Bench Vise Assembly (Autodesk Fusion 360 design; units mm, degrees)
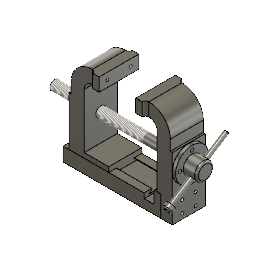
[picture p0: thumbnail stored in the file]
sketch "Sketch1" plane through (0, 0, 0) normal (0, 0, 1) x axis (1, 0, 0)
  line L1 (295, 0) -> (0, 0)
  line L2 (295, 64) -> (295, 0)
  line L3 (275, 64) -> (295, 64)
  line L4 (275, 27) -> (275, 64)
  line L5 (245, 27) -> (275, 27)
  line L6 (245, 42) -> (245, 27)
  line L7 (0, 42) -> (245, 42)
  line L8 (0, 0) -> (0, 42)
  point P1 (0, 0)
  point P2 (0, 0)
  point P3 (295, 0)
  point P4 (295, 64)
  point P5 (275, 64)
  point P9 (0, 42)
  point P6 (275, 27)
  point P7 (245, 27)
  coincident P1 P2
  horizontal L1
  perpendicular L1 L2
  perpendicular L2 L3
  perpendicular L3 L4
  perpendicular L4 L5
  perpendicular L5 L6
  perpendicular L6 L7
  perpendicular L1 L8
  dimension "d1" distance P2 P3 = 295
  dimension "d2" distance P3 P4 = 64
  dimension "d3" distance P4 P5 = 20
  dimension "d4" distance L1 L5 = 27
  dimension "d5" distance P2 P9 = 42
  dimension "d6" distance P6 P7 = 30
extrude "Extrude1" new body sketch "Sketch1" distance 100
sketch "Sketch2" plane through (0, 0, 0) normal (-1, 0, 0) x axis (0, 0, 1)
  line L1 (50, 0) -> (-50, 0)
  line L2 (50, 42) -> (50, 0)
  line L3 (-50, 42) -> (50, 42)
  line L4 (-50, 0) -> (-50, 42)
  line L5 (0, 68.3047) -> (0, 0)
  line L6 (-27, 40) -> (-27, 42)
  line L7 (-35, 32) -> (-27, 40)
  line L8 (35, 32) -> (-35, 32)
  line L9 (27, 40) -> (35, 32)
  line L10 (27, 42) -> (27, 40)
  line L11 (27, 42) -> (-27, 42)
  point P1 (0, 0)
  point P6 (0, 0)
  point P8 (-27, 42)
  point P13 (27, 42)
  point P10 (-35, 32)
  point P11 (35, 32)
  point P9 (-27, 40)
  coincident P1 P6
  perpendicular L1 L5
  coincident L3 P8
  perpendicular L3 L6
  perpendicular L6 L8
  perpendicular L7 L9
  coincident L3 P13
  vertical L10
  symmetric L5 L6 L10
  equal L6 L10
  symmetric L5 P10 P11
  dimension "d9" distance P8 P13 = 54
  dimension "d10" distance P10 P11 = 70
  dimension "d11" distance P8 P9 = 2
extrude "Extrude2" cut sketch "Sketch2" profile of L3 L6 L7 L8 L9 L10 L11 to an object
sketch "Sketch3" plane through (295, 0, 0) normal (1, 0, 0) x axis (0, 0, -1)
  line L1 (-50, 64) -> (50, 64)
  line L2 (-50, 0) -> (-50, 64)
  line L3 (50, 0) -> (-50, 0)
  line L4 (50, 64) -> (50, 0)
  line L5 (0, 88.8318) -> (0, 0)
  point P1 (0, 0)
  point P6 (0, 0)
  point P8 (-20, 52)
  point P9 (20, 52)
  point P10 (20, 16)
  point P11 (-20, 16)
  coincident P1 P6
  perpendicular L3 L5
  symmetric L5 P8 P9
  symmetric L5 P10 P11
  vertical P8 P11
  dimension "d14" distance P8 P9 = 40
  dimension "d15" distance P8 P11 = 36
  dimension "d16" distance L3 P11 = 16
hole "Hole1" HoleDepth 20 HoleDiameter 9 TipAngle 118
sketch "Sketch1" plane through (0, 0, 0) normal (-1, 0, 0) x axis (0, 0, 1)
  line L1 (-27, 42) -> (-27, 40)
  line L2 (-50, 42) -> (-27, 42)
  line L3 (-50, 0) -> (-50, 42)
  line L4 (50, 0) -> (-50, 0)
  line L5 (50, 42) -> (50, 0)
  line L6 (27, 42) -> (50, 42)
  line L7 (27, 40) -> (27, 42)
  line L8 (35, 32) -> (27, 40)
  line L9 (-35, 32) -> (35, 32)
  line L10 (-27, 40) -> (-35, 32)
  line L11 (-27, 42) -> (-27, 40)
  line L12 (-27, 40) -> (-35, 32)
  line L13 (-35, 32) -> (35, 32)
  line L14 (35, 32) -> (27, 40)
  line L15 (27, 40) -> (27, 42)
  line L16 (-50, 42) -> (-27, 42)
  line L17 (27, 42) -> (50, 42)
  line L18 (-50, 57) -> (-50, 42)
  line L19 (50, 57) -> (-50, 57)
  line L20 (50, 42) -> (50, 57)
  point P18 (-50, 42)
  point P20 (-50, 42)
  point P19 (50, 42)
  point P23 (50, 42)
  coincident P18 P20
  perpendicular L16 L18
  perpendicular L5 L19
  coincident P19 P23
  perpendicular L17 L20
  dimension "d20" distance L13 L19 = 25
extrude "Extrude1" new body sketch "Sketch1" profile of L1 L2 L6 L7 L8 L9 L10 L11 L12 L13 L14 L15 L16 L17 L18 L19 L20 against normal blind 120
sketch "Sketch2" plane through (0, 0, 50) normal (0, 0, 1) x axis (1, 0, 0)
  line L1 (0, 42) -> (0, 57)
  line L2 (120, 42) -> (0, 42)
  line L3 (120, 57) -> (120, 42)
  line L4 (0, 57) -> (120, 57)
  line L5 (0, 190) -> (0, 57)
  line L6 (6, 190) -> (0, 190)
  line L7 (6, 222) -> (6, 190)
  line L8 (101, 287) -> (71, 287)
  line L9 (101, 247) -> (101, 287)
  line L10 (71, 247) -> (101, 247)
  line L11 (46, 57) -> (46, 222)
  line L12 (0, 57) -> (46, 57)
  arc A1 centre (71, 222) radius 65 clockwise from (6, 222) to (71, 287)
  arc A2 centre (71, 222) radius 25 clockwise from (46, 222) to (71, 247)
  point P2 (0, 57)
  point P6 (0, 57)
  point P17 (46, 57)
  point P7 (0, 190)
  point P8 (6, 190)
  point P9 (6, 222)
  point P10 (71, 287)
  point P12 (101, 287)
  coincident P2 P6
  perpendicular L4 L5
  perpendicular L5 L6
  perpendicular L6 L7
  tangent L7 A1
  horizontal L8
  tangent A1 L8
  perpendicular L8 L9
  perpendicular L9 L10
  tangent L10 A2
  coincident L4 P17
  perpendicular L5 L12
  vertical L11
  concentric A1 A2
  tangent A2 L11
  dimension "d24" distance P7 P8 = 6
  dimension "d25" distance P8 P9 = 32
  dimension "d26" radius A1 = 65
  dimension "d27" distance P10 P12 = 30
  dimension "d28" radius A2 = 25
  dimension "d65" distance L8 L12 = 230
extrude "Extrude2" add sketch "Sketch2" profile of L4 L5 L6 L7 A1 L8 L9 L10 A2 L11 L12 to an object
sketch "Sketch3" plane through (0, 0, 50) normal (0, 0, 1) x axis (1, 0, 0)
  line L1 (0, 42) -> (0, 190)
  line L2 (120, 42) -> (0, 42)
  line L3 (120, 57) -> (120, 42)
  line L4 (46, 57) -> (120, 57)
  line L5 (46, 222) -> (46, 57)
  line L6 (101, 247) -> (71, 247)
  line L7 (101, 287) -> (101, 247)
  line L8 (71, 287) -> (101, 287)
  line L9 (6, 190) -> (6, 222)
  line L10 (0, 190) -> (6, 190)
  line L11 (81, 287) -> (101, 287)
  line L12 (81, 247) -> (81, 287)
  line L13 (101, 247) -> (81, 247)
  line L14 (101, 287) -> (101, 247)
  arc A1 centre (71, 222) radius 25 clockwise from (46, 222) to (71, 247)
  arc A2 centre (71, 222) radius 65 clockwise from (6, 222) to (71, 287)
  point P17 (81, 247)
  point P11 (101, 287)
  point P15 (101, 287)
  point P16 (81, 287)
  horizontal L11
  vertical L12
  horizontal L13
  vertical L14
  coincident L6 P17
  coincident P11 P15
  dimension "d31" distance P15 P16 = 20
extrude "Extrude3" add sketch "Sketch3" profile of L6 L7 L8 L11 L12 L13 L14 along normal blind 10
mirror "Mirror1"
fillet "Fillet1" radius 10
sketch "Sketch4" plane through (46, 0, 0) normal (1, 0, 0) x axis (0, 0, -1)
  line L1 (50, 222) -> (50, 57)
  line L2 (-50, 222) -> (50, 222)
  line L3 (-50, 57) -> (-50, 222)
  line L4 (50, 57) -> (-50, 57)
  line L5 (-50, 57) -> (50, 57)
  circle C1 centre (0, 139) radius 15
  point P1 (0, 0)
  point P6 (0, 139)
  vertical P1 P6
  dimension "d36" diameter C1 = 30
  dimension "d37" distance P6 L5 = 82
extrude "Extrude4" cut sketch "Sketch4" profile of C1 no distance stored
sketch "Sketch5" plane through (101, 0, 0) normal (1, 0, 0) x axis (0, 0, -1)
  line L1 (-60, 287) -> (60, 287)
  line L2 (-60, 247) -> (-60, 287)
  line L3 (60, 247) -> (-60, 247)
  line L4 (60, 287) -> (60, 247)
  line L5 (0, 297.2184) -> (0, 0)
  point P1 (0, 0)
  point P6 (0, 0)
  point P8 (-35, 267)
  point P9 (35, 267)
  coincident P1 P6
  perpendicular L1 L5
  symmetric L5 P8 P9
  dimension "d39" distance P8 P9 = 70
  dimension "d40" distance L3 P8 = 20
hole "Hole1" HoleDepth 12 HoleDiameter 9 TipAngle 118
sketch "Sketch1" plane through (0, 0, 50) normal (0, 0, 1) x axis (1, 0, 0)
  line L1 (0, 0) -> (0, 42)
  line L2 (295, 0) -> (0, 0)
  line L3 (295, 64) -> (295, 0)
  line L4 (275, 64) -> (295, 64)
  line L5 (275, 27) -> (275, 64)
  line L6 (245, 27) -> (275, 27)
  line L7 (245, 42) -> (245, 27)
  line L8 (0, 42) -> (245, 42)
  line L9 (275, 64) -> (295, 64)
  line L10 (295, 64) -> (295, 0)
  line L11 (330, 0) -> (295, 0)
  line L12 (330, 190) -> (330, 0)
  line L13 (324, 190) -> (330, 190)
  line L14 (324, 222) -> (324, 190)
  line L15 (229, 287) -> (259, 287)
  line L16 (229, 247) -> (229, 287)
  line L17 (259, 247) -> (229, 247)
  line L18 (284, 64) -> (284, 222)
  arc A1 centre (259, 222) radius 65 clockwise from (259, 287) to (324, 222)
  arc A2 centre (259, 222) radius 25 clockwise from (259, 247) to (284, 222)
  point P4 (295, 0)
  point P13 (295, 0)
  point P25 (284, 64)
  point P14 (330, 0)
  point P15 (330, 190)
  point P16 (324, 190)
  point P17 (324, 222)
  point P18 (259, 287)
  point P20 (229, 287)
  coincident P4 P13
  perpendicular L10 L11
  perpendicular L11 L12
  perpendicular L12 L13
  perpendicular L13 L14
  tangent L14 A1
  perpendicular L10 L15
  perpendicular L15 L16
  perpendicular L16 L17
  tangent L17 A2
  tangent A1 L15
  concentric A1 A2
  vertical L18
  tangent A2 L18
  coincident L4 P25
  dimension "d44" distance P14 P15 = 190
  dimension "d45" distance P13 P14 = 35
  dimension "d46" distance P16 P17 = 32
  dimension "d47" radius A1 = 65
  dimension "d48" distance P18 P20 = 30
  dimension "d49" radius A2 = 25
  dimension "d51" distance L12 L18 = 46
extrude "Extrude1" new body sketch "Sketch1" profile of L3 L4 L9 L10 L11 L12 L13 L14 A1 L15 L16 L17 A2 L18 to an object
sketch "Sketch2" plane through (0, 0, 50) normal (0, 0, 1) x axis (1, 0, 0)
  line L1 (330, 0) -> (295, 0)
  line L2 (330, 190) -> (330, 0)
  line L3 (324, 190) -> (330, 190)
  line L4 (324, 222) -> (324, 190)
  line L5 (229, 287) -> (259, 287)
  line L6 (229, 247) -> (229, 287)
  line L7 (259, 247) -> (229, 247)
  line L8 (284, 64) -> (284, 222)
  line L9 (295, 64) -> (284, 64)
  line L10 (295, 0) -> (295, 64)
  line L11 (249, 287) -> (229, 287)
  line L12 (249, 247) -> (249, 287)
  line L13 (229, 247) -> (249, 247)
  line L14 (229, 287) -> (229, 247)
  arc A1 centre (259, 222) radius 65 clockwise from (259, 287) to (324, 222)
  arc A2 centre (259, 222) radius 25 clockwise from (259, 247) to (284, 222)
  point P17 (249, 247)
  point P9 (229, 287)
  point P15 (229, 287)
  point P16 (249, 287)
  horizontal L11
  vertical L12
  horizontal L13
  vertical L14
  coincident L7 P17
  coincident P9 P15
  dimension "d54" distance P15 P16 = 20
extrude "Extrude2" add sketch "Sketch2" profile of L5 L6 L7 L11 L12 L13 L14 along normal blind 10
mirror "Mirror1"
fillet "Fillet1" radius 10
sketch "Sketch3" plane through (229, 0, 0) normal (-1, 0, 0) x axis (0, 0, 1)
  line L1 (60, 247) -> (-60, 247)
  line L2 (60, 287) -> (60, 247)
  line L3 (-60, 287) -> (60, 287)
  line L4 (-60, 247) -> (-60, 287)
  line L5 (0, 317.3095) -> (0, 0)
  point P1 (0, 0)
  point P6 (0, 0)
  point P8 (-35, 267)
  point P9 (35, 267)
  coincident P1 P6
  perpendicular L3 L5
  symmetric L5 P8 P9
  dimension "d59" distance P8 P9 = 70
  dimension "d61" distance L1 P8 = 20
hole "Hole1" HoleDepth 12 HoleDiameter 9 TipAngle 118
sketch "Sketch5" plane through (330, 0, 0) normal (1, 0, 0) x axis (0, 0, -1)
  line L1 (50, 190) -> (50, 0)
  line L2 (-50, 190) -> (50, 190)
  line L3 (-50, 0) -> (-50, 190)
  line L4 (50, 0) -> (-50, 0)
  circle C1 centre (0, 139) radius 15
extrude "Extrude3" cut sketch "Sketch5" profile of C1 to an object
sketch "Sketch6" plane through (330, 0, 0) normal (1, 0, 0) x axis (0, 0, -1)
  line L1 (50, 190) -> (50, 0)
  line L2 (-50, 190) -> (50, 190)
  line L3 (-50, 0) -> (-50, 190)
  line L4 (50, 0) -> (-50, 0)
  circle C1 centre (0, 139) radius 15
  circle C2 centre (0, 176) radius 5
  circle C3 centre (0, 139) radius 37
  point P7 (0, 176)
  point P8 (0, 139)
  concentric C1 C3
  coincident P7 C3
  vertical P7 P8
  dimension "d70" diameter C3 = 74
  dimension "d71" diameter C2 = 10
extrude "Extrude4" cut sketch "Sketch6" profile of C2 to an object
circular_pattern "C-Pattern1" TotalAngle 360
sketch "Sketch1" plane through (330, 0, 0) normal (1, 0, 0) x axis (0, 0, -1)
  line L1 (50, 190) -> (50, 0)
  line L2 (-50, 190) -> (50, 190)
  line L3 (-50, 0) -> (-50, 190)
  line L4 (50, 0) -> (-50, 0)
  circle C1 centre (-37, 139) radius 5
  circle C2 centre (0, 102) radius 5
  circle C3 centre (37, 139) radius 5
  circle C4 centre (0, 176) radius 5
  circle C5 centre (0, 139) radius 15
  circle C6 centre (0, 139) radius 50
  circle C7 centre (-37, 139) radius 5
  circle C8 centre (0, 176) radius 5
  circle C9 centre (37, 139) radius 5
  circle C10 centre (0, 102) radius 5
  circle C11 centre (0, 139) radius 15
  concentric C5 C6
  dimension "d76" diameter C6 = 100
extrude "Extrude1" new body sketch "Sketch1" profile of C1 C2 C3 C4 C5 C6 C7 C8 C9 C10 C11 along normal blind 10
sketch "Sketch1" plane through (340, 0, 0) normal (1, 0, 0) x axis (0, 0, -1)
  circle C1 centre (0, 176) radius 5
  circle C2 centre (37, 139) radius 5
  circle C3 centre (0, 139) radius 15
  circle C4 centre (-37, 139) radius 5
  circle C5 centre (0, 102) radius 5
  circle C6 centre (0, 139) radius 50
  circle C7 centre (0, 139) radius 15
extrude "Extrude1" new body sketch "Sketch1" profile of C3 C7 against normal blind 415
sketch "Sketch2" plane through (340, 0, 0) normal (1, 0, 0) x axis (0, 0, -1)
  circle C1 centre (0, 139) radius 15
  circle C2 centre (0, 139) radius 27
  concentric C1 C2
  dimension "d81" diameter C2 = 54
extrude "Extrude2" add sketch "Sketch2" along normal blind 40
sketch "Sketch3" plane through (0, 0, 0) normal (0, 0, 1) x axis (1, 0, 0)
  line L1 (380, 166) -> (380, 112)
  circle C1 centre (360, 139) radius 7
  point P2 (360, 139)
  point P4 (380, 166)
  dimension "d84" diameter C1 = 14
  dimension "d85" distance P2 L1 = 20
  dimension "d86" distance P2 P4 = 27 (= "( 54 / 2 ) * 1 mm")
extrude "Extrude3" cut sketch "Sketch3" profile of C1 no distance stored
fillet "Fillet1" radius 6
thread "Thread1" ThreadOffset 0 ThreadLength 280
sketch "Sketch1" plane through (0, 0, 0) normal (0, 0, 1) x axis (1, 0, 0)
  line L1 (380, 118) -> (380, 160)
  circle C1 centre (360, 139) radius 7
  point P2 (360, 139)
  point P3 (380, 160)
  dimension "d92" diameter C1 = 14
  dimension "d93" distance P2 L1 = 20
  dimension "d94" distance P2 P3 = 21 (= "( 42 / 2 ) * 1 mm")
extrude "Extrude1" new body sketch "Sketch1" profile of C1 distance 200
sketch "Sketch2" plane through (0, 0, 100) normal (0, 0, 1) x axis (1, 0, 0)
  circle C1 centre (360, 139) radius 7
  circle C2 centre (360, 139) radius 12.5
  concentric C1 C2
  dimension "d97" diameter C2 = 25
extrude "Extrude2" add sketch "Sketch2" along normal blind 15
fillet "Fillet1" radius 4
chamfer "Chamfer1" distance 2 rotateAngle 45
ground "Ground1"
as_built_joint "As-built1"
as_built_joint "As-built2"
as_built_joint "As-built3" OffsetX 0 OffsetY 0 OffsetZ 0 AngleZ 0
as_built_joint "As-built4"
as_built_joint "As-built6" OffsetX 0 OffsetY 0 OffsetZ 0 AngleZ 0 DistanceMinimum -125 DistanceMaximum 80
motion_link "MotionLink1" Value1 360 Value2 200
sketch "Sketch7" plane through (330, 0, 0) normal (1, 0, 0) x axis (0, 0, -1)
  line L1 (50, 190) -> (50, 0)
  line L2 (-50, 190) -> (50, 190)
  line L3 (-50, 0) -> (-50, 190)
  line L4 (50, 0) -> (-50, 0)
  circle C1 centre (-37, 139) radius 5
  circle C2 centre (0, 102) radius 5
  circle C3 centre (37, 139) radius 5
  circle C4 centre (0, 176) radius 5
  circle C5 centre (0, 139) radius 15
  circle C6 centre (-20, 16) radius 4.263
  circle C7 centre (-20, 16) radius 4.263
  circle C8 centre (-20, 52) radius 4.263
  circle C9 centre (-20, 52) radius 4.263
  circle C10 centre (20, 52) radius 4.263
  circle C11 centre (20, 52) radius 4.263
  circle C12 centre (20, 16) radius 4.263
hole "Hole2" HoleDepth 35 HoleDiameter 9 TipAngle 180
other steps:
thread "Thread1"
thread "Thread1"
thread "Thread1"
thread "Thread2"
create_component "CreateComponent1"
create_component "CreateComponent2"
create_component "CreateComponent3"
create_component "CreateComponent4"
create_component "CreateComponent5"
create_component "CreateComponent6"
